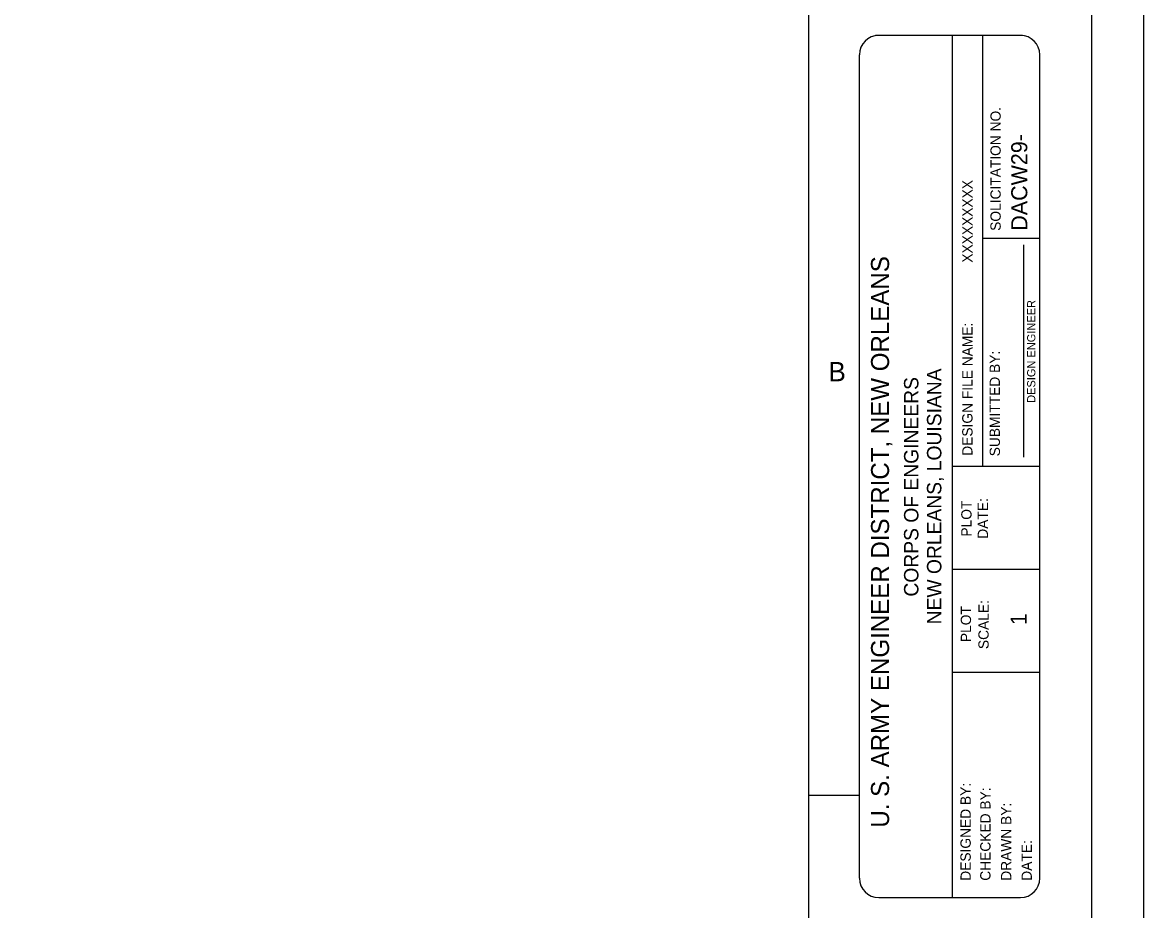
# Model space of a CAD drawing. Extents: x 22369.62 to 22376.4, y 22369.62 to 22372.46.
# Drawn here: x 22372.38 to 22373.288, y 22370.257 to 22370.976 of the extents above; entities that cross this region are included whole.
import ezdxf

# ---------------------------------------------------------------- set-up
doc = ezdxf.new("R2010")
doc.units = 0
for name, color, linetype in [('Level 1', 7, 'Continuous'), ('Level 10', 7, 'Continuous'), ('Level 2', 7, 'Continuous'), ('Level 7', 7, 'Continuous'), ('Level 9', 7, 'Continuous')]:
    doc.layers.add(name, color=color, linetype=linetype)

msp = doc.modelspace()

# ---------------------------------------------------------------- linework, layer by layer
at = {"layer": 'Level 1'}
for p, q in [((22373.19, 22370.9653), (22373.071, 22370.9653)), ((22373.133, 22370.9653), (22373.133, 22370.2673))]:
    msp.add_line(p, q, dxfattribs=at)
msp.add_lwpolyline([(22369.6213, 22372.4553), (22373.288, 22372.4553), (22373.288, 22369.6213), (22369.6213, 22369.6213)], close=True, dxfattribs=at)
for points in [[(22373.18837, 22370.9653), (22373.07362, 22370.9653)], [(22373.058, 22370.28293), (22373.058, 22370.94968)], [(22373.204, 22370.28293), (22373.204, 22370.94968)], [(22373.07362, 22370.2673), (22373.18837, 22370.2673)]]:
    msp.add_lwpolyline(points, dxfattribs=at)
for centre, radius, start, end in [((22373.07362, 22370.94968), 0.01563, 90, 180), ((22373.18837, 22370.94968), 0.01562, 0, 90), ((22373.07362, 22370.28293), 0.01562, 180, 270), ((22373.18837, 22370.28293), 0.01562, 270, 0)]:
    msp.add_arc(centre, radius, start, end, dxfattribs=at)
at = {"layer": 'Level 10'}
msp.add_line((22373.017, 22370.3503), (22373.058, 22370.3503), dxfattribs=at)
at = {"layer": 'Level 2'}
for p, q in [((22373.15757, 22370.9653), (22373.15757, 22370.6163)), ((22373.204, 22370.801), (22373.15757, 22370.801)), ((22373.191, 22370.62386), (22373.191, 22370.79563)), ((22373.204, 22370.6163), (22373.133, 22370.6163)), ((22373.204, 22370.53297), (22373.133, 22370.53297)), ((22373.204, 22370.44963), (22373.133, 22370.44963))]:
    msp.add_line(p, q, dxfattribs=at)
at = {"layer": 'Level 9'}
msp.add_line((22373.246, 22369.6633), (22373.246, 22372.4133), dxfattribs=at)
msp.add_lwpolyline([(22373.017, 22369.6633), (22373.017, 22372.4133)], dxfattribs=at)

# ---------------------------------------------------------------- texts
at = {"layer": 'Level 1'}
for s, height, p in [('SOLICITATION NO.', 0.0083339, (22373.17235, 22370.80707)), ('XXXXXXXXX', 0.008333, (22373.14953, 22370.78132)), ('U. S. ARMY ENGINEER DISTRICT, NEW ORLEANS', 0.0145832, (22373.08194, 22370.32393)), ('DESIGN ENGINEER', 0.0066659, (22373.20038, 22370.66784)), ('DESIGN FILE NAME:', 0.0083339, (22373.14951, 22370.625)), ('SUBMITTED BY:', 0.0083339, (22373.17172, 22370.62457)), ('PLOT', 0.008334, (22373.14873, 22370.55956)), ('DATE:', 0.008334, (22373.16203, 22370.55782)), ('SCALE:', 0.008334, (22373.1626, 22370.46849)), ('PLOT', 0.008334, (22373.14832, 22370.47414)), ('DESIGNED BY:', 0.0083339, (22373.14808, 22370.28095)), ('CHECKED BY:', 0.0083339, (22373.16408, 22370.28095)), ('DRAWN BY:', 0.008334, (22373.1809, 22370.28095)), ('DATE:', 0.008334, (22373.19756, 22370.28095))]:
    msp.add_text(s, height=height, rotation=90, dxfattribs=at).set_placement(p)
msp.add_text('B', height=0.01561, dxfattribs=at).set_placement((22373.033, 22370.6853))
at = {"layer": 'Level 7'}
for s, height, p in [('DACW29-', 0.013, (22373.19386, 22370.80718)), ('NEW ORLEANS, LOUISIANA', 0.0116666, (22373.1243, 22370.4885)), ('CORPS OF ENGINEERS', 0.0116666, (22373.10572, 22370.51098)), ('1', 0.013, (22373.1933, 22370.48788))]:
    msp.add_text(s, height=height, rotation=90, dxfattribs=at).set_placement(p)

doc.saveas('drawing.dxf')
